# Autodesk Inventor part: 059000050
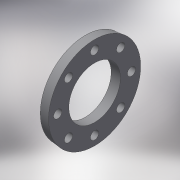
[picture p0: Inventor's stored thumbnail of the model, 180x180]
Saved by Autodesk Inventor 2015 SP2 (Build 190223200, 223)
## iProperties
Created: 2017-10
Part Number: 059000050
Material: Generic
Description: PLASSON BACKING FLANGE PVC 50
Document SubType Name: Modeling
Designer: KIM
Density: 1 g/cm^3
Appearance: Default
Author: KIM
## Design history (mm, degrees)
derived "059000.ipt"
feature "Solid1::059000.ipt"
tag "TaggingFeature1"
body "Solid1"
other parameters: "d0" = 16, "d1" = 65, "d3" = 147, "d5" = 18, "d6" = 55, "d7" = 16, "d8" = 0, "d10" = 360 deg, "E_" = 65, "H_" = 16, "S_" = 18
